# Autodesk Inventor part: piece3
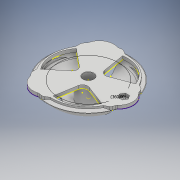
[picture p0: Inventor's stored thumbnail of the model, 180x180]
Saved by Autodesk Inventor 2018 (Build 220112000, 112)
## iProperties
Created: 2018-12
Part Number: piece3
Material: Generic
Document SubType Name: Modeling
Designer: thierry.jost
Density: 1 g/cm^3
Appearance: Default
Author: thierry.jost
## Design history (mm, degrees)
sketch "Sketch1"
  geometry: L1 (0, 81.56)-(0, -81.56); L2 (64, -50.557)-(63.27, -50.557); L3 (63.27, -50.557)-(58.27, -48.557); L4 (58.27, -45.557)-(58.27, -48.557); L5 (58.27, -45.557)-(56.37, -45.557); L6 (56.37, -45.557)-(56.37, -51.221); L7 (16.215, -50.657)-(16.215, -75.783); L8 (16.215, -50.657)-(11.74, -50.657); L9 (11.74, -45.557)-(8, -45.557); L10 (11.74, -50.657)-(11.74, -45.557); L11 (8, -45.557)-(8, -81.167); A1 r 81.56 centre (0, 0) between (-64, -50.557) and (64, -50.557); A2 r 59.07 centre (11.28, -16.92) between (8, -75.899) and (53.521, -58.211); A3 r 10 centre (46.37, -51.221) between (53.521, -58.211) and (56.37, -51.221); 3 further points
  constraints: 22 end point, 10 point on circle, 6 vertical, 4 horizontal, 3 centre point, 3 point on line, 2 tangent, 1 coincident, 1 collinear
  dimensions: "d0" = 163.12 diameter of A1; "d1" = 128 distance of A1.start L2.start; "d3" = 158.2 deg angle of L3 L2; "d5" = 3 distance from line of L5 L3.end; "d6" = 1.9 distance between parallel lines of L6 L4; "d9" = 16.92 vertical distance of A1.centre A2.centre; "d10" = 118.14 diameter of A2; "d11" = 11.28 horizontal distance of A2.centre A1.centre; "d13" = 10 radius of A3; "d15" = 5.1 distance between parallel lines of L5 L8; "d17" = 16 diameter of L11 L1
revolve "Revolution1" sketch "Sketch1" stored, may be unused: angle "d12" = 90 deg
fillet "Fillet1" dims "d18" = 1
workplane "Work Plane1"
sketch "Sketch2"
  geometry: L1 (9, -5.196)-(0, -10.392); L2 (0, -10.392)-(-9, -5.196); L3 (-9, -5.196)-(-9, 5.196); L4 (-9, 5.196)-(0, 10.392); L5 (0, 10.392)-(9, 5.196); L6 (9, 5.196)-(9, -5.196); 2 further points
  constraints: 12 end point, 1 coincident, 13 other
  dimensions: "d20" = 18 distance between parallel lines of L6 L3
extrude "Extrusion1" cut sketch "Sketch2" extent not by distance; stored distance "d21" = 10; taper "d22" = -4 deg
fillet "Fillet2" dims "d23" = 5
fillet "Fillet3" dims "d24" = 0.5
fillet "Fillet4" dims "d25" = 1
sketch "Sketch5"
  geometry: L1 (56.854, 24.679)-(51.102, 28); L2 (51.102, 28)-(51.102, 83.66); L3 (0, 0)-(72.619, 0); L4 (56.854, -24.679)-(51.102, -28); L5 (-7.055, 61.577)-(-1.302, 58.255); L6 (-49.8, 36.898)-(-49.8, 30.255); L7 (-49.8, -36.898)-(-49.8, -30.255); L8 (-7.055, -61.577)-(-1.302, -58.255); C1 r 63.27 at (0, 0) reference; C2 r 8.5 at (0, 0) reference; A1 r 22.5 centre (46.5, 0) between (61.982, -16.326) and (61.982, 16.326); A2 r 63.27 centre (0, 0) between (59.496, -21.524) and (60.385, -18.889); A3 r 63.27 centre (0, 0) between (60.385, 18.889) and (59.496, 21.524); A4 r 6 centre (53.854, 19.483) between (59.496, 21.524) and (56.854, 24.679); A5 r 6 centre (66.111, 20.68) between (60.385, 18.889) and (61.982, 16.326); A6 r 6 centre (53.854, -19.483) between (56.854, -24.679) and (59.496, -21.524); A7 r 63.27 centre (0, 0) between (59.496, -21.524) and (60.385, -18.889); A8 r 6 centre (66.111, -20.68) between (61.982, -16.326) and (60.385, -18.889); A9 r 22.5 centre (-23.25, 40.27) between (-16.852, 61.841) and (-45.13, 45.515); A10 r 6 centre (-15.146, 67.594) between (-16.852, 61.841) and (-13.834, 61.739); A11 r 63.27 centre (0, 0) between (-11.108, 62.287) and (-13.834, 61.739); A12 r 63.27 centre (0, 0) between (-11.108, 62.287) and (-13.834, 61.739); A13 r 6 centre (-10.055, 56.38) between (-7.055, 61.577) and (-11.108, 62.287); A14 r 6 centre (-43.8, 36.898) between (-48.388, 40.763) and (-49.8, 36.898); A15 r 6 centre (-50.965, 46.914) between (-46.55, 42.85) and (-45.13, 45.515); A16 r 63.27 centre (0, 0) between (-46.55, 42.85) and (-48.388, 40.763); A17 r 22.5 centre (-23.25, -40.27) between (-45.13, -45.515) and (-16.852, -61.841); A18 r 6 centre (-50.965, -46.914) between (-45.13, -45.515) and (-46.55, -42.85); A19 r 63.27 centre (0, 0) between (-48.388, -40.763) and (-46.55, -42.85); A20 r 63.27 centre (0, 0) between (-48.388, -40.763) and (-46.55, -42.85); A21 r 6 centre (-43.8, -36.898) between (-49.8, -36.898) and (-48.388, -40.763); A22 r 6 centre (-10.055, -56.38) between (-11.108, -62.287) and (-7.055, -61.577); A23 r 6 centre (-15.146, -67.594) between (-13.834, -61.739) and (-16.852, -61.841); A24 r 63.27 centre (0, 0) between (-13.834, -61.739) and (-11.108, -62.287); A25 r 58.27 centre (0, 0) between (-1.302, -58.255) and (51.102, -28); A26 r 58.27 centre (0, 0) between (51.102, 28) and (-1.302, 58.255); A27 r 58.27 centre (0, 0) between (-49.8, 30.255) and (-49.8, -30.255); 6 further points
  constraints: 57 point on circle, 27 centre point, 16 end point, 7 symmetric about line, 4 tangent, 3 point on line, 2 coincident, 1 equal radius, 1 horizontal, 1 vertical, 88 other
  dimensions: "d45" = 45 diameter of A1; "d46" = 46.5 distance of C1.centre A1.centre; "d47" = 120 deg angle of L1 L2; "d48" = 28 vertical distance of L3.start L1.end; "d50" = 6 radius of A4 (derived); "d53" = 360 deg dimension on A25.centre L3.end (derived)
extrude "Extrusion3" join sketch "Sketch5" distance "d55" = 5; taper "d56" = 0 deg
sketch "Sketch6"
  geometry: L1 (-66.621, 6.2)-(-93.001, 27.714); L2 (-66.621, -6.2)-(-93.001, -27.714); C1 r 8 at (-46.5, 0) reference; A1 r 43.85 centre (-59.02, 0) between (-93.001, 27.714) and (-93.001, -27.714); A2 r 8 centre (-71.678, 0) between (-66.621, -6.2) and (-66.621, 6.2); 1 further point
  constraints: 4 end point, 4 point on circle, 2 centre point, 2 point on line, 2 tangent
  dimensions: "d58" = 87.7 diameter of A1; "d59" = 12.52 distance of A1.centre C1.centre; "d62" = 8 radius of A2
extrude "Extrusion4" cut sketch "Sketch6" distance "d63" = 10; taper "d64" = 0 deg
pattern_circular "Circular Pattern1" dims angle "d66" = 360 deg
sketch "Sketch7"
  geometry: L1 (5.26, -5.908)-(1.764, -0.148); L2 (1.764, -0.148)-(5.004, 5.759); L3 (5.004, 5.759)-(11.74, 5.908); L4 (11.74, 5.908)-(15.236, 0.148); L5 (15.236, 0.148)-(11.996, -5.759); L6 (11.996, -5.759)-(5.26, -5.908); 2 further points
  constraints: 12 end point, 13 other
  dimensions: "d68" = 11.67 distance between parallel lines of L3 L6; "d69" = 55 distance of point (-46.5, 0) point (8.5, 0)
extrude "Extrusion5" cut sketch "Sketch7" distance "d70" = 7; taper "d71" = 3 deg
sketch "Sketch8"
  geometry: L1 (-80.461, -28.788)-(-29.5, -13.499); L2 (-29.5, 0)-(-80.461, 0); L3 (-29.5, -13.499)-(-29.5, 0); L4 (-80.461, -28.788)-(-80.461, 0); L5 (-80.461, 28.788)-(-29.5, 13.499); L6 (-80.461, 28.788)-(-80.461, 0); L7 (-29.5, 13.499)-(-29.5, 0); 1 further point
  constraints: 14 end point, 2 symmetric about line, 1 horizontal, 1 perpendicular, 1 vertical
  dimensions: "d72" = 16.7 deg angle of L2 L1; "d73" = 29.5 distance from line of point (0, 0) L3; "d76" = 0 distance from line of point (0, 0) L2
extrude "Extrusion6" cut sketch "Sketch8" extent not by distance; stored distance "d74" = 10; taper "d75" = 0 deg
pattern_circular "Circular Pattern2" dims angle "d78" = 360 deg
sketch "Sketch9"
  geometry: L1 (-47.252, -26.414)-(-15.43, -14.326) reference; L2 (-4.692, -20.525)-(0.751, -54.129) reference; L3 (-15.43, 14.326)-(-47.252, 26.414) reference; L4 (0.751, 54.129)-(-4.692, 20.525) reference; L5 (20.121, 6.2)-(46.501, 27.714) reference; L6 (46.501, -27.714)-(20.121, -6.2) reference; L7 (8.595, -55.711)-(10.355, -63.157) reference; L8 (49.518, -40.546)-(43.95, -35.299) reference; L9 (43.95, -35.299)-(41.87, -33.338) reference; L10 (-52.544, 20.412)-(-59.873, 22.611) reference; L11 (-59.873, -22.611)-(-52.544, -20.412) reference; L12 (43.95, 35.299)-(49.518, 40.546) reference; L13 (10.355, 63.157)-(8.595, 55.711) reference; C1 r 22.5 at (-46.5, 0); C2 r 16.215 at (0, 0) reference; C3 r 22.5 at (23.25, -40.27); C4 r 22.5 at (23.25, 40.27); A1 r 22.5 centre (-46.5, 0) between (-61.982, 16.326) and (-61.982, -16.326) reference; A2 r 8 centre (-12.589, -21.804) between (-4.692, -20.525) and (-15.43, -14.326) reference; A3 r 8 centre (-12.589, 21.804) between (-15.43, 14.326) and (-4.692, 20.525) reference; A4 r 8 centre (25.178, 0) between (20.121, 6.2) and (20.121, -6.2) reference; A5 r 56.37 centre (0, 0) between (-28.185, -48.818) and (8.595, -55.711) reference; A6 r 56.37 centre (0, 0) between (-28.185, 48.818) and (-52.544, 20.412) reference; A7 r 56.37 centre (0, 0) between (-52.544, -20.412) and (-28.185, -48.818) reference; A8 r 56.37 centre (0, 0) between (56.37, 0) and (43.95, 35.299) reference; A9 r 56.37 centre (0, 0) between (8.595, 55.711) and (-28.185, 48.818) reference; 1 further point
  constraints: 3 centre point, 2 concentric, 7 other
  dimensions: "d82" = 360 deg dimension on C2.centre C1.centre (derived)
body "Solid1"
other parameters: "d4" = 5.73, "d14" = 32.43, "d16" = 23.48, "d19" = -18, "d49" = 116.54
